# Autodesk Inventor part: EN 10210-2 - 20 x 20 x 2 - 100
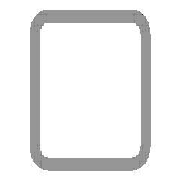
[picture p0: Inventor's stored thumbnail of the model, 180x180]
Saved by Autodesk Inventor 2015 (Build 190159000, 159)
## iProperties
Created: 2015-05
Part Number: EN 10210-2 - 20 x 20 x 2 - 100
Material: Steel, Mild
Description: Tube
Document SubType Name: Modeling
Standard: DIN
Designer: TREINA6
Standard Revision: 1997
Standards Organization: DIN
Language: en-US
Size Designation: 20 x 20 x 2
Categories: <MemberInstance><Categories><Category DisplayName="Structural Shapes" InternalName="089c4875-fa83-4c05-b084-43b9cc11f5ed" Mnemonic="GRDR"><CategoryParameter Dis
Stock Number: 20 x 20 x 2
Density: 7.85 g/cm^3
Appearance: Semi-Polished
_CCFamilyMember: 1
_CCFamilyDisplayName: DIN EN 10210-2 (Square) - Tube
_FrameMemberDoc: Frame Member File
_Version: 15.0.0
_GetPNFromCC: 1
IsCustomPart: 1
Author: TREINA6
G_L: 100,000 mm
G_W: 20,000 mm
G_H: 20,000 mm
+9808EFAD-8F49-4AFE-891C-7ED121EBB028+CUTDETAIL1: Miter 45,00 deg
+9A0701DD-5C28-48D1-9548-9F52B9A0137C+CUTDETAIL2: Miter 45,00 deg
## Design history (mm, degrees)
node "Start plane"
node "End plane"
sketch "Sketch"
  geometry: L1 (-10, -7)-(-10, 7); L2 (-7, 10)-(7, 10); L3 (10, 7)-(10, -7); L4 (7, -10)-(-7, -10); L5 (-7, 8)-(7, 8); L6 (8, 7)-(8, -7); L7 (7, -8)-(-7, -8); L8 (-8, -7)-(-8, 7); L9 (0, 14.87)-(0, -14.87) reference; L10 (-14.87, 0)-(14.87, 0) reference; A1 r 3 centre (-7, -7) between (-10, -7) and (-7, -10); A2 r 3 centre (-7, 7) between (-7, 10) and (-10, 7); A3 r 3 centre (7, 7) between (10, 7) and (7, 10); A4 r 3 centre (7, -7) between (7, -10) and (10, -7); A5 r 1 centre (-7, 7) between (-7, 8) and (-8, 7); A6 r 1 centre (7, 7) between (8, 7) and (7, 8); A7 r 1 centre (7, -7) between (7, -8) and (8, -7); A8 r 1 centre (-7, -7) between (-8, -7) and (-7, -8)
  constraints: 16 end point, 16 point on circle, 8 centre point, 8 tangent, 4 parallel, 3 equal radius, 2 perpendicular, 7 other
  dimensions: "d7" = 3 radius of A1 (= G_IR); "d10" = 20 distance between parallel lines of L2 L4 (= G_H); "d11" = 20 distance between parallel lines of L1 L3 (= G_W); "d12" = 2 distance between parallel lines of L3 L6 (= G_T); "d15" = 10 distance between parallel lines of L2 L10 (= 0.5 x d10); "d16" = 10 distance between parallel lines of L9 L3 (= 0.5 x d11)
extrude "Body" new body sketch "Sketch" stored distance "d3" = 100 (= G_L); taper "d4" = 0 deg
node "Driven Length"
  sketch "Sketch3"
    geometry: L1 (0, 0)-(10, 0) reference
    constraints: 2 end point, 1 horizontal
  workplane "Work Plane3"
  sketch "Sketch4"
    geometry: L1 (-2, 0)-(12, 0) reference; L2 (-2, 100)-(12, 100) reference
    dimensions: "d18" = 100 distance between parallel lines of L1 L2 (derived)
workplane "Work Plane4"
split "Split1"
workplane "Work Plane5"
split "Split2"
body "Solid1"
other parameters: "G_W" = 20 [user parameter; used in 1 equation term], "G_H" = 20 [user parameter; used in 1 equation term], "G_T" = 2 [user parameter; used in 1 equation term], "G_IR" = 3 [user parameter; used in 1 equation term], "G_L" = 100 (= d18) [user parameter; used in 1 equation term], "G_OFFSET_START" = 0 [user parameter; used in 1 equation term], "G_OFFSET_END" = 0 [user parameter; used in 1 equation term], "d13" = 0 (computed from G_OFFSET_START), "d17" = 90 deg
